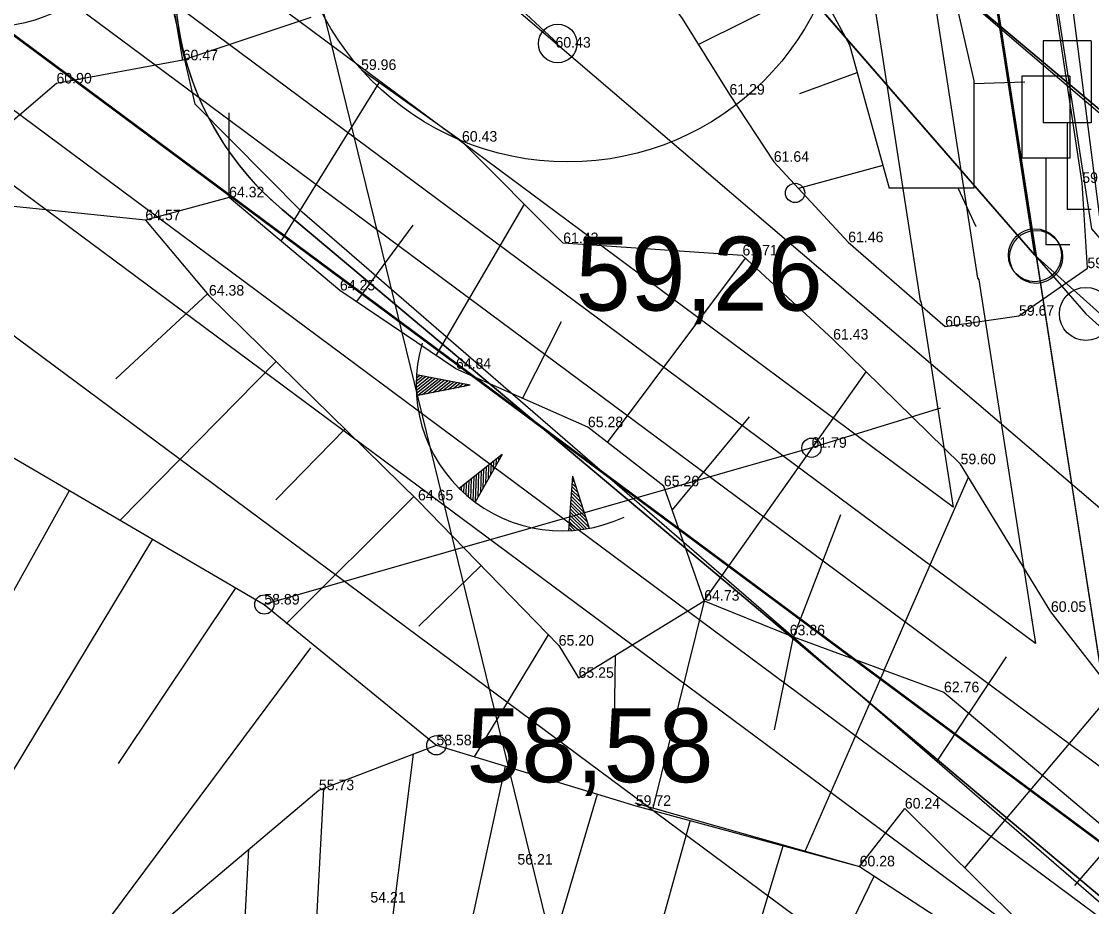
# Model space of a CAD drawing. Extents: x 700746 to 706058, y 6570320 to 6580460.
# Drawn here: x 703133.4 to 703168.92, y 6577150.7 to 6577180.08 of the extents above; entities that cross this region are included whole.
import ezdxf

# ---------------------------------------------------------------- set-up
doc = ezdxf.new("R2010")
doc.units = 0
for name, color, linetype in [('HALJASTUS', 7, 'Continuous'), ('illumineerimisjooned', 7, 'Continuous'), ('Kaitsevöönd', 7, 'Continuous'), ('kataster', 7, 'Continuous'), ('KORGUS-EH2000', 7, 'Continuous'), ('KPOHULIIN', 7, 'Continuous'), ('LIIKLUS', 7, 'Continuous'), ('Lõige', 7, 'Continuous'), ('maeeraldised_kehtivad', 7, 'Continuous'), ('MOOTKORG-EH2000', 7, 'Continuous'), ('mäeeraldis', 7, 'Continuous'), ('mäeeraldise teenindusmaa', 7, 'Continuous'), ('PIIR', 7, 'Continuous'), ('Plokid', 7, 'Continuous'), ('POST', 7, 'Continuous'), ('RELJEEF', 7, 'Continuous'), ('TEE', 7, 'Continuous'), ('Tmaad_maeeraldised_kehtivad', 7, 'Continuous'), ('VWX2_MV_PLOKK', 7, 'Continuous')]:
    doc.layers.add(name, color=color, linetype=linetype)

msp = doc.modelspace()

# ---------------------------------------------------------------- linework, layer by layer
at = {"layer": 'HALJASTUS'}
msp.add_lwpolyline([(703163.904, 6577167.241), (703159.622, 6577165.927), (703141.459, 6577160.724)], dxfattribs=at)
at = {"layer": 'illumineerimisjooned'}
for points in [[(703281.213, 6577072.058), (703170.159, 6577171.774), (703168.929, 6577173.195), (703127.168, 6577443.561), (702857.567, 6577467.93), (702860.381, 6577440.007), (702861.165, 6577378.171)], [(702863.784, 6577290.018), (702865.214, 6577375.332), (702864.385, 6577440.164), (702864.379, 6577440.224), (702864.379, 6577440.233), (702862.035, 6577463.486), (703118.822, 6577440.287), (703124.016, 6577437.389), (703150.875, 6577263.871), (703165.133, 6577171.562), (703165.173, 6577171.504), (703167.053, 6577159.433)], [(702862.311, 6577373.596), (702850.89, 6577377.293), (702839.79, 6577379.563), (702831.646, 6577378.473), (702820.821, 6577374.823), (702754.92, 6577346.017), (702742.145, 6577342.939), (702732.615, 6577342.189), (702714.765, 6577344.588), (702715.658, 6577336.409), (703090.802, 6577213.589), (703232.719, 6577108.158), (703252.344, 6577093.719)], [(702976.891, 6576643.26), (702915.328, 6577059.558), (702785.772, 6577104.455), (702748.407, 6577249.47), (702721.642, 6577298.043), (702716.252, 6577332.033), (702861.102, 6577284.56), (703066.328, 6577217.365), (703088.858, 6577210.018), (703169.031, 6577150.466), (703230.271, 6577104.95), (703275.453, 6577071.675), (703358.033, 6576531.935)], [(703167.053, 6577159.433), (703091.733, 6577215.389), (702863.784, 6577290.018)], [(703290.041, 6576963.147), (703188.508, 6577001.438), (703016.934, 6577112.515), (702852.033, 6577230.395), (702862.776, 6577281.723), (703065.707, 6577215.464), (703087.928, 6577208.218), (703167.838, 6577148.861), (703229.081, 6577103.342), (703273.601, 6577070.555), (703290.041, 6576963.147)]]:
    msp.add_lwpolyline(points, dxfattribs=at)
at = {"layer": 'Kaitsevöönd'}
for points in [[(703332.065, 6576694.743), (703304.442, 6576872.638), (703273.694, 6577070.52), (703230.233, 6577104.832), (703217.52, 6577108.973), (703142.719, 6577173.75), (703139.166, 6577177.33), (703138.297, 6577181.096), (703138.49, 6577185.153), (703140.421, 6577188.437), (703144.379, 6577190.851), (703147.661, 6577191.817), (703151.812, 6577191.141), (703154.805, 6577189.403), (703166.583, 6577179.261), (703228.658, 6577126.14), (703241.595, 6577121.215), (703289.275, 6577083.661), (703291.813, 6577080.846), (703293.137, 6577077.314), (703294.406, 6577068.373), (703355.652, 6576672.76)], [(703154.91, 6577189.152), (703230.532, 6577125.647), (703239.404, 6577123.376), (703292.869, 6577081.186), (703317.705, 6576917.046)], [(703317.705, 6576917.046), (703292.869, 6577081.186), (703239.404, 6577123.376), (703230.532, 6577125.647), (703154.91, 6577189.152)], [(703297.93, 6576914.054), (703274.276, 6577070.381), (703230.34, 6577105.051), (703221.159, 6577107.401), (703142.048, 6577173.836)], [(703142.048, 6577173.836), (703221.159, 6577107.401), (703230.34, 6577105.051), (703274.276, 6577070.381), (703297.93, 6576914.054)]]:
    msp.add_lwpolyline(points, dxfattribs=at)
for start in [49.9774, 83.3344]:
    msp.add_arc((703148.479, 6577181.494), 10, start, 229.9774, dxfattribs=at)
at = {"layer": 'kataster'}
for points in [[(703360.09, 6576531.99), (703277.36, 6577072.83), (703167.04, 6577172.32), (703125.43, 6577441.71), (702859.8, 6577465.72), (702862.38, 6577440.12), (702863.2, 6577375.41), (702851.4, 6577379.23), (702839.86, 6577381.59), (702831.19, 6577380.43), (702820.1, 6577376.69), (702754.28, 6577347.92), (702741.83, 6577344.92), (702732.67, 6577344.2), (702712.5, 6577346.91), (702704.73, 6577347.96), (702701.8, 6577345.85), (702700.78, 6577341.43), (702712.4, 6577226.51), (702651.69, 6577159.42), (702595.69, 6577121.68), (702628.71, 6576895.25), (702720.42, 6576547.28)], [(702754.28, 6577347.92), (702820.1, 6577376.69), (702831.19, 6577380.43), (702839.86, 6577381.59), (702851.4, 6577379.23), (702863.2, 6577375.41), (702878.06, 6577370.59), (702900.72, 6577367.74), (702944.77, 6577367.92), (702961.68, 6577364.05), (703005.04, 6577344.66), (703019.19, 6577342.06), (703041.25, 6577339.7), (703057.1, 6577329.85), (703096.08, 6577280.59), (703119.31, 6577233.95), (703129.16, 6577218.59), (703141.54, 6577201.64), (703167.04, 6577172.32), (703168.73, 6577170.37), (703277.36, 6577072.83), (703231.53, 6577106.55), (703089.87, 6577211.79), (702713.81, 6577334.91)]]:
    msp.add_lwpolyline(points, dxfattribs=at)
for points in [[(702859.8, 6577465.72), (703125.43, 6577441.71), (703167.04, 6577172.32), (703141.54, 6577201.64), (703129.16, 6577218.59), (703119.31, 6577233.95), (703096.08, 6577280.59), (703057.1, 6577329.85), (703041.25, 6577339.7), (703019.19, 6577342.06), (703005.04, 6577344.66), (702961.68, 6577364.05), (702944.77, 6577367.92), (702900.72, 6577367.74), (702878.06, 6577370.59), (702863.2, 6577375.41), (702862.38, 6577440.12)], [(702852.27, 6575508.89), (702837.26, 6575620.73), (702848.38, 6575976.59), (702782.85, 6576063.35), (702782.57, 6576096.37), (702842.53, 6576210.56), (702853.4, 6576267.5), (702844.46, 6576489.93), (702877.29, 6576548.25), (702974.72, 6576643.9), (702913.57, 6577058.07), (702784.04, 6577102.84), (702746.48, 6577248.7), (702719.69, 6577297.36), (702713.81, 6577334.91), (703089.87, 6577211.79), (703231.53, 6577106.55), (703277.36, 6577072.83), (703360.09, 6576531.99), (703311.6, 6576228.52), (703293.62, 6575965.66), (703298.84, 6575573.29)]]:
    msp.add_lwpolyline(points, close=True, dxfattribs=at)
at = {"layer": 'KORGUS-EH2000'}
for centre in [(703159.078, 6577174.386), (703159.622, 6577165.927), (703141.459, 6577160.724), (703147.17, 6577156.05)]:
    msp.add_circle(centre, 0.32, dxfattribs=at)
at = {"layer": 'KPOHULIIN'}
msp.add_lwpolyline([(703223.684, 6577117.354), (703148.385, 6577181.716), (703152.38, 6577187.98), (703142.541, 6577213.827), (703139.767, 6577237.383)], dxfattribs=at)
at = {"layer": 'LIIKLUS'}
for p, q in [((703167.308, 6577179.437), (703167.308, 6577176.717)), ((703168.908, 6577179.437), (703167.308, 6577179.437)), ((703167.308, 6577179.437), (703167.308, 6577176.717)), ((703168.908, 6577179.437), (703167.308, 6577179.437)), ((703167.308, 6577179.437), (703167.308, 6577176.717)), ((703168.908, 6577179.437), (703167.308, 6577179.437)), ((703168.908, 6577179.437), (703168.908, 6577176.717)), ((703168.908, 6577179.437), (703168.908, 6577176.717)), ((703168.908, 6577179.437), (703168.908, 6577176.717)), ((703166.602, 6577178.266), (703166.602, 6577175.546)), ((703168.202, 6577178.266), (703166.602, 6577178.266)), ((703166.602, 6577178.266), (703166.602, 6577175.546)), ((703168.202, 6577178.266), (703166.602, 6577178.266)), ((703166.602, 6577178.266), (703166.602, 6577175.546)), ((703168.202, 6577178.266), (703166.602, 6577178.266)), ((703168.202, 6577178.266), (703168.202, 6577175.546)), ((703168.202, 6577178.266), (703168.202, 6577175.546)), ((703168.202, 6577178.266), (703168.202, 6577175.546)), ((703168.908, 6577176.717), (703167.308, 6577176.717)), ((703168.908, 6577176.717), (703167.308, 6577176.717)), ((703168.908, 6577176.717), (703167.308, 6577176.717)), ((703168.108, 6577176.717), (703168.108, 6577173.837)), ((703168.108, 6577176.717), (703168.108, 6577173.837)), ((703168.108, 6577176.717), (703168.108, 6577173.837)), ((703168.202, 6577175.546), (703166.602, 6577175.546)), ((703168.202, 6577175.546), (703166.602, 6577175.546)), ((703168.202, 6577175.546), (703166.602, 6577175.546)), ((703167.402, 6577175.546), (703167.402, 6577172.666)), ((703167.402, 6577175.546), (703167.402, 6577172.666)), ((703167.402, 6577175.546), (703167.402, 6577172.666)), ((703168.908, 6577173.837), (703168.108, 6577173.837)), ((703168.908, 6577173.837), (703168.108, 6577173.837)), ((703168.908, 6577173.837), (703168.108, 6577173.837)), ((703168.202, 6577172.666), (703167.402, 6577172.666)), ((703168.202, 6577172.666), (703167.402, 6577172.666)), ((703168.202, 6577172.666), (703167.402, 6577172.666))]:
    msp.add_line(p, q, dxfattribs=at)
at = {"layer": 'Lõige'}
msp.add_lwpolyline([(703132.186, 6577226.247), (703187.674, 6576999.687)], dxfattribs=at)
at = {"layer": 'maeeraldised_kehtivad'}
msp.add_lwpolyline([(702849.808, 6577229.527), (702861.724, 6577286.461), (703066.949, 6577219.266), (703089.789, 6577211.819), (703170.224, 6577152.072), (703231.46, 6577106.558), (703277.305, 6577072.795), (703294.683, 6576959.259), (703187.602, 6576999.642), (703015.809, 6577110.861)], close=True, dxfattribs=at)
at = {"layer": 'mäeeraldis'}
msp.add_lwpolyline([(702859.802, 6577465.696), (703119.425, 6577442.241), (703125.486, 6577438.859), (703125.878, 6577438.438), (703152.852, 6577264.176), (703167.04, 6577172.32), (703167.079, 6577172.263), (703170.22, 6577152.098), (703089.87, 6577211.79), (702861.725, 6577286.484), (702863.214, 6577375.336), (702862.386, 6577440.049), (702862.38, 6577440.109), (702862.38, 6577440.12), (702859.802, 6577465.696)], dxfattribs=at)
at = {"layer": 'mäeeraldise teenindusmaa'}
msp.add_lwpolyline([(702859.8, 6577465.72), (703125.43, 6577441.71), (703167.04, 6577172.32), (703168.73, 6577170.37), (703277.36, 6577072.83), (703231.53, 6577106.55), (703089.87, 6577211.79), (702713.81, 6577334.91), (702712.5, 6577346.91), (702732.67, 6577344.2), (702741.83, 6577344.92), (702754.28, 6577347.92), (702820.1, 6577376.69), (702831.19, 6577380.43), (702839.86, 6577381.59), (702851.4, 6577379.23), (702863.2, 6577375.41), (702862.38, 6577440.12), (702859.8, 6577465.72)], dxfattribs=at)
at = {"layer": 'PIIR'}
for centre, radius in [((703151.534, 6577184.618), 9.2), ((703167.04, 6577172.32), 0.88), ((703167.04, 6577172.32), 0.88), ((703167.04, 6577172.32), 0.88), ((703167.079, 6577172.263), 0.88), ((703167.079, 6577172.263), 0.88), ((703168.73, 6577170.37), 0.88)]:
    msp.add_circle(centre, radius, dxfattribs=at)
at = {"layer": 'Plokid'}
msp.add_lwpolyline([(703043.339, 6577445.098), (703121.898, 6577438.001), (703148.899, 6577263.565), (703163.227, 6577170.805), (703163.267, 6577170.746), (703164.325, 6577163.951), (703092.665, 6577217.188), (702865.809, 6577291.46), (702867.214, 6577375.329), (702866.384, 6577440.28), (702866.378, 6577440.34), (702866.377, 6577440.346), (702864.268, 6577461.276), (703043.339, 6577445.098)], dxfattribs=at)
msp.add_lwpolyline([(703287.547, 6576966.226), (703189.415, 6577003.234), (703018.06, 6577114.169), (702854.258, 6577231.263), (702863.9, 6577277.331), (703064.465, 6577211.662), (703086.067, 6577204.618), (703165.453, 6577145.65), (703226.702, 6577100.127), (703272.178, 6577066.636)], close=True, dxfattribs=at)
at = {"layer": 'POST'}
msp.add_line((703148.685, 6577181.687), (703151.199, 6577179.347), dxfattribs=at)
msp.add_circle((703151.199, 6577179.347), 0.64, dxfattribs=at)
at = {"layer": 'RELJEEF'}
for p, q in [((703159.814, 6577181.28), (703155.87, 6577179.31)), ((703159.235, 6577177.692), (703161.14, 6577178.386)), ((703142.023, 6577172.785), (703145.271, 6577178.043)), ((703165.016, 6577178.015), (703166.708, 6577178.074)), ((703140.29, 6577174.24), (703140.29, 6577177.05)), ((703161.991, 6577175.302), (703159.194, 6577174.529)), ((703165.09, 6577173.259), (703164.486, 6577174.545)), ((703137.51, 6577173.48), (703130.434, 6577174.216)), ((703147.167, 6577168.991), (703150.091, 6577174.013)), ((703146.386, 6577173.318), (703144.515, 6577170.782)), ((703152.849, 6577166.105), (703157.427, 6577172.22)), ((703136.527, 6577168.212), (703139.574, 6577171.035)), ((703151.311, 6577170.105), (703150.026, 6577167.573)), ((703141.855, 6577168.79), (703136.679, 6577163.519)), ((703146.495, 6577168.034), (703146.813, 6577168.288)), ((703146.496, 6577167.932), (703146.917, 6577168.268)), ((703146.497, 6577168.137), (703146.71, 6577168.308)), ((703146.499, 6577167.831), (703147.02, 6577168.248)), ((703146.501, 6577168.243), (703146.607, 6577168.328)), ((703146.503, 6577167.733), (703147.123, 6577168.228)), ((703148.288, 6577168.003), (703146.507, 6577168.347)), ((703156.06, 6577160.85), (703161.436, 6577168.447)), ((703148.288, 6577168.003), (703146.508, 6577167.654)), ((703146.541, 6577167.661), (703147.226, 6577168.209)), ((703146.711, 6577167.694), (703147.329, 6577168.189)), ((703146.881, 6577167.727), (703147.432, 6577168.169)), ((703147.05, 6577167.76), (703147.535, 6577168.149)), ((703147.22, 6577167.794), (703147.639, 6577168.129)), ((703147.39, 6577167.827), (703147.742, 6577168.109)), ((703147.559, 6577167.86), (703147.845, 6577168.089)), ((703147.729, 6577167.894), (703147.948, 6577168.069)), ((703147.898, 6577167.927), (703148.051, 6577168.049)), ((703148.068, 6577167.96), (703148.154, 6577168.029)), ((703157.557, 6577166.95), (703154.996, 6577163.868)), ((703141.837, 6577164.2), (703144.14, 6577166.551)), ((703149.35, 6577165.699), (703147.928, 6577164.573)), ((703149.35, 6577165.699), (703148.455, 6577164.122)), ((703148.983, 6577165.053), (703148.996, 6577165.419)), ((703149.069, 6577165.203), (703149.079, 6577165.484)), ((703149.154, 6577165.354), (703149.161, 6577165.549)), ((703149.239, 6577165.504), (703149.243, 6577165.614)), ((703148.471, 6577164.151), (703148.502, 6577165.027)), ((703148.557, 6577164.301), (703148.585, 6577165.093)), ((703148.642, 6577164.452), (703148.667, 6577165.158)), ((703148.727, 6577164.602), (703148.749, 6577165.223)), ((703148.813, 6577164.752), (703148.832, 6577165.288)), ((703148.898, 6577164.903), (703148.914, 6577165.353)), ((703148.081, 6577164.428), (703148.091, 6577164.701)), ((703148.159, 6577164.359), (703148.173, 6577164.766)), ((703148.236, 6577164.293), (703148.255, 6577164.832)), ((703148.314, 6577164.23), (703148.338, 6577164.897)), ((703148.392, 6577164.169), (703148.42, 6577164.962)), ((703151.693, 6577164.982), (703151.558, 6577163.173)), ((703151.814, 6577164.604), (703151.675, 6577164.741)), ((703151.762, 6577164.769), (703151.683, 6577164.846)), ((703151.693, 6577164.982), (703152.246, 6577163.255)), ((703162.03, 6577158.545), (703164.83, 6577164.956)), ((703129.563, 6577154.764), (703134.987, 6577164.508)), ((703148.003, 6577164.5), (703148.008, 6577164.636)), ((703152.025, 6577163.945), (703151.644, 6577164.322)), ((703151.972, 6577164.11), (703151.652, 6577164.427)), ((703151.92, 6577164.275), (703151.66, 6577164.532)), ((703151.867, 6577164.439), (703151.667, 6577164.637)), ((703146.426, 6577164.311), (703142.181, 6577160.083)), ((703152.183, 6577163.452), (703151.62, 6577164.008)), ((703152.131, 6577163.616), (703151.628, 6577164.113)), ((703152.078, 6577163.781), (703151.636, 6577164.218)), ((703152.071, 6577163.225), (703151.597, 6577163.694)), ((703152.169, 6577163.241), (703151.605, 6577163.799)), ((703152.236, 6577163.287), (703151.612, 6577163.903)), ((703160.59, 6577163.699), (703159.028, 6577159.653)), ((703151.662, 6577163.179), (703151.565, 6577163.275)), ((703151.768, 6577163.187), (703151.573, 6577163.38)), ((703151.871, 6577163.198), (703151.581, 6577163.484)), ((703151.972, 6577163.21), (703151.589, 6577163.589)), ((703137.75, 6577162.893), (703129.18, 6577148.7)), ((703146.588, 6577160.01), (703148.656, 6577162.016)), ((703136.622, 6577155.451), (703140.502, 6577161.257)), ((703156.06, 6577160.85), (703154.361, 6577153.967)), ((703150.883, 6577159.718), (703148.42, 6577155.671)), ((703158.398, 6577156.568), (703159.028, 6577159.653)), ((703142.992, 6577159.282), (703133.94, 6577147.14)), ((703153.077, 6577156.094), (703153.121, 6577159.045)), ((703166.088, 6577158.992), (703164.844, 6577157.115)), ((703162.03, 6577158.545), (703159.399, 6577152.523)), ((703167.291, 6577155.052), (703169.633, 6577157.83)), ((703163.79, 6577155.524), (703164.844, 6577157.115)), ((703144.998, 6577144.526), (703146.411, 6577155.76)), ((703149.454, 6577155.356), (703144.491, 6577132.441)), ((703167.291, 6577155.052), (703164.703, 6577151.983)), ((703143.422, 6577154.618), (703142.37, 6577134.68)), ((703149.1, 6577142.804), (703152.516, 6577154.427)), ((703155.594, 6577153.552), (703148.676, 6577128.611)), ((703168.358, 6577151.391), (703169.737, 6577152.99)), ((703140.507, 6577144.403), (703140.948, 6577152.601)), ((703154.81, 6577139.833), (703158.683, 6577152.716)), ((703161.699, 6577151.717), (703150.072, 6577127.585))]:
    msp.add_line(p, q, dxfattribs=at)
for points in [[(703142.924, 6577284.56), (703143.223, 6577275.568), (703143.689, 6577260.194), (703140.595, 6577257.457), (703139.165, 6577254.614), (703138.491, 6577248.811), (703136.14, 6577242.577), (703135.743, 6577233.147), (703136.396, 6577222.748), (703143.342, 6577214.959), (703149.897, 6577199.564), (703160.887, 6577179.302), (703162.2, 6577174.545)], [(703146.058, 6577246.504), (703149.389, 6577243.41), (703152.047, 6577222.632), (703161.522, 6577193.337), (703165.016, 6577178.113), (703165.016, 6577174.545), (703162.2, 6577174.545)], [(703168.61, 6577174.72), (703165.795, 6577193.289), (703162.804, 6577217.735)], [(703134.07, 6577215.59), (703135.81, 6577217.04), (703137.17, 6577216.5), (703140.61, 6577213.1), (703141.92, 6577209.67), (703142.93, 6577208.14), (703143.64, 6577205.22), (703143.31, 6577202.02), (703142.12, 6577198.98), (703142.5, 6577194.54), (703144.01, 6577192.51), (703144.86, 6577188.46), (703148.22, 6577187.29), (703151.79, 6577185.17), (703153.31, 6577182.88), (703155.33, 6577180.18), (703156.9, 6577177.65), (703158.37, 6577175.42), (703160.84, 6577172.75), (703164.06, 6577169.95), (703166.51, 6577170.31), (703168.78, 6577171.89), (703168.61, 6577174.72)], [(703138.75, 6577178.79), (703138.15, 6577182.4), (703139.79, 6577186.64), (703139.98, 6577191.02)], [(703143, 6577180.21), (703138.75, 6577178.79), (703134.56, 6577178.02), (703130.79, 6577174.8), (703127.27, 6577169.02), (703127.27, 6577169.02), (703127.27, 6577169.02)], [(703172.24, 6577154.48), (703167.57, 6577160.48), (703164.57, 6577165.38), (703160.34, 6577169.52), (703157.33, 6577172.31), (703151.38, 6577172.72), (703148.02, 6577176.09), (703144.67, 6577178.47)], [(703156.06, 6577160.85), (703154.72, 6577164.65), (703152.2, 6577166.61), (703147.82, 6577168.55), (703143.97, 6577171.15), (703140.29, 6577174.24), (703137.51, 6577173.48)], [(703137.51, 6577173.48), (703139.62, 6577170.98), (703146.56, 6577164.18), (703151.23, 6577159.36), (703151.89, 6577158.29), (703156.06, 6577160.85)], [(703122.58, 6577172.87), (703127.27, 6577169.02), (703141.459, 6577160.724), (703147.17, 6577156.05), (703147.17, 6577156.05)], [(703156.06, 6577160.85), (703158.9, 6577159.7), (703164.02, 6577157.81), (703171.03, 6577151.9)], [(703121.02, 6577146.33), (703129.18, 6577148.7), (703133.94, 6577147.14), (703137.07, 6577149.33), (703143.27, 6577154.56), (703147.17, 6577156.05), (703153.79, 6577154.04), (703161.22, 6577152.03), (703166.63, 6577148.5), (703170.75, 6577144.36)], [(703153.759, 6577154.137), (703161.22, 6577152.03), (703161.22, 6577152.03), (703162.72, 6577153.95), (703166.49, 6577150.21), (703170.5, 6577146.78)]]:
    msp.add_lwpolyline(points, dxfattribs=at)
for centre in [(703132.456, 6577184.774), (703151.339, 6577168.012)]:
    msp.add_arc(centre, 4.844, 163.4234, 295.1745, dxfattribs=at)
at = {"layer": 'TEE'}
msp.add_lwpolyline([(703179.547, 6577161.139), (703169.238, 6577173.243), (703166.626, 6577193.534), (703160.2, 6577240.722), (703156.38, 6577266.088), (703153.719, 6577285.507), (703150.718, 6577307.59), (703147.903, 6577328.419), (703144.69, 6577353.776), (703142.202, 6577374.784), (703138.648, 6577403.985), (703135.913, 6577420.188), (703128.933, 6577436.507), (703124.739, 6577441.153), (703117.207, 6577443.572), (703095.164, 6577447.556), (703070.81, 6577452.482), (703060.985, 6577457.375), (703058.261, 6577465.436), (703059.512, 6577486.172), (703058.55, 6577494.083), (703056.075, 6577498.724), (703049.697, 6577503.274), (703043.823, 6577504.615)], dxfattribs=at)
at = {"layer": 'Tmaad_maeeraldised_kehtivad'}
msp.add_lwpolyline([(702974.764, 6576643.974), (702913.527, 6577058.065), (702784.103, 6577102.917), (702746.534, 6577248.726), (702719.722, 6577297.384), (702713.764, 6577334.953), (702861.724, 6577286.461), (703066.949, 6577219.266), (703089.789, 6577211.819), (703089.789, 6577211.819), (703170.224, 6577152.072), (703231.46, 6577106.558), (703277.305, 6577072.795), (703360.057, 6576531.928)], dxfattribs=at)
at = {"layer": 'VWX2_MV_PLOKK'}
for points in [[(703222.9, 6577490.69), (703314.13, 6577060.15), (703296.09, 6577067.87), (703170.22, 6577152.1), (703125.37, 6577441.7), (703121.85, 6577464.43), (703121.06, 6577464.52), (703074.97, 6577705.03), (703364.79, 6577738.24)], [(702859.74, 6577465.7), (703125.37, 6577441.7), (703167.08, 6577172.26), (703170.22, 6577152.07), (703089.79, 6577211.82), (702861.72, 6577286.46), (702863.21, 6577375.33), (702862.39, 6577440.05)], [(702859.74, 6577465.7), (703125.37, 6577441.7), (703167.08, 6577172.26), (703170.22, 6577152.07), (703089.79, 6577211.82), (702861.72, 6577286.46), (702863.21, 6577375.33), (702862.39, 6577440.05)], [(703044.07, 6577449.05), (703125.37, 6577441.7), (703167.08, 6577172.26), (703170.22, 6577152.1), (703231.53, 6577106.55), (703277.36, 6577072.83), (703360.09, 6576531.99), (703311.6, 6576228.52), (703293.62, 6575965.66), (703294.04, 6575933.77), (703295.43, 6575829.7), (703298.36, 6575609.6), (703298.84, 6575573.29), (703155.29, 6575552.59), (703145.59, 6575981.92), (703123.04, 6576234.88), (703120.61, 6576749.6), (703011.59, 6576989.47), (703015.74, 6577110.88), (702996.73, 6577210.32)], [(702849.88, 6577229.56), (702861.72, 6577286.46), (703066.96, 6577219.29), (703089.79, 6577211.82), (703170.22, 6577152.07), (703231.53, 6577106.55), (703277.36, 6577072.83), (703294.74, 6576959.21), (703187.67, 6576999.67), (703015.74, 6577110.88)], [(702849.88, 6577229.56), (702861.72, 6577286.46), (703066.96, 6577219.29), (703089.79, 6577211.82), (703170.22, 6577152.07), (703231.53, 6577106.55), (703277.36, 6577072.83), (703294.74, 6576959.21), (703187.67, 6576999.67), (703015.74, 6577110.88)]]:
    msp.add_lwpolyline(points, close=True, dxfattribs=at)

# ---------------------------------------------------------------- texts
at = {"layer": 'KORGUS-EH2000'}
for s, p in [('59,26', (703151.795, 6577170.482)), ('58,58', (703148.17, 6577154.825))]:
    msp.add_text(s, height=2.45, dxfattribs=at).set_placement(p)
at = {"layer": 'MOOTKORG-EH2000'}
for s, p in [('60.43', (703151.124, 6577179.211)), ('60.47', (703138.75, 6577178.79)), ('59.96', (703144.67, 6577178.47)), ('60.90', (703134.56, 6577178.02)), ('61.29', (703156.9, 6577177.65)), ('60.43', (703148.02, 6577176.09)), ('61.64', (703158.37, 6577175.42)), ('59.69', (703168.61, 6577174.72)), ('64.32', (703140.29, 6577174.24)), ('64.57', (703137.51, 6577173.48)), ('61.43', (703151.38, 6577172.72)), ('61.46', (703160.84, 6577172.75)), ('61.71', (703157.33, 6577172.31)), ('59.79', (703168.78, 6577171.89)), ('64.25', (703143.97, 6577171.15)), ('64.38', (703139.62, 6577170.98)), ('59.67', (703166.51, 6577170.31)), ('60.50', (703164.06, 6577169.95)), ('61.43', (703160.34, 6577169.52)), ('64.84', (703147.82, 6577168.55)), ('65.28', (703152.2, 6577166.61)), ('61.79', (703159.622, 6577165.927)), ('59.60', (703164.57, 6577165.38)), ('65.26', (703154.72, 6577164.65)), ('64.65', (703146.56, 6577164.18)), ('64.73', (703156.06, 6577160.85)), ('58.89', (703141.459, 6577160.724)), ('60.05', (703167.57, 6577160.48)), ('63.86', (703158.9, 6577159.7)), ('65.20', (703151.23, 6577159.36)), ('65.25', (703151.89, 6577158.29)), ('62.76', (703164.02, 6577157.81)), ('58.58', (703147.17, 6577156.05)), ('55.73', (703143.27, 6577154.56)), ('59.72', (703153.79, 6577154.04)), ('60.24', (703162.72, 6577153.95)), ('56.21', (703149.86, 6577152.09)), ('60.28', (703161.22, 6577152.03)), ('54.21', (703144.98, 6577150.83))]:
    msp.add_text(s, height=0.35, dxfattribs=at).set_placement(p)

doc.saveas('drawing.dxf')
